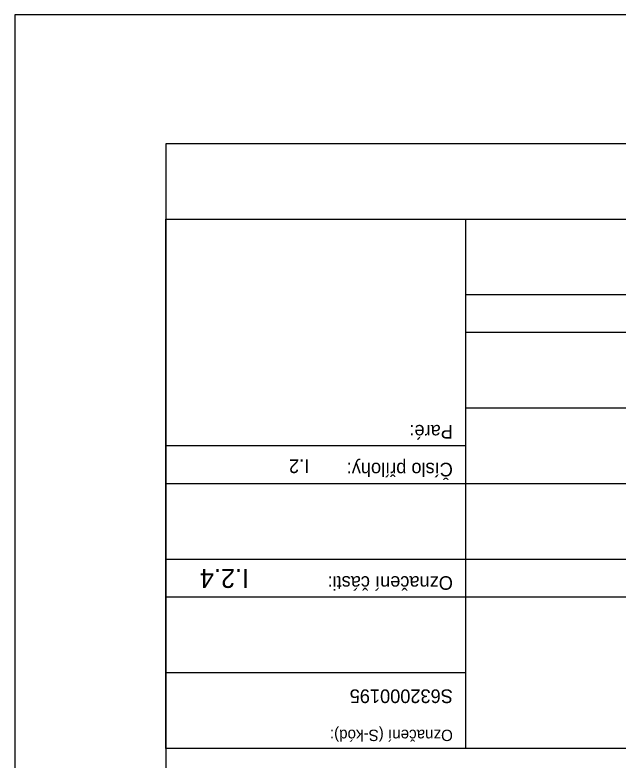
# Model space of a CAD drawing. Extents: x -728452 to -728347, y -1073107 to -1072959.
# Drawn here: x -728452.31 to -728412.4, y -1073008.07 to -1072958.8 of the extents above; entities that cross this region are included whole.
import ezdxf

# ---------------------------------------------------------------- set-up
doc = ezdxf.new("R2010")
doc.units = 0
for name, color, linetype in [('Default', 7, 'Continuous'), ('Dočasný_do_1_roku_PUPFL', 7, 'Continuous'), ('Ořez', 7, 'Continuous')]:
    doc.layers.add(name, color=color, linetype=linetype)

msp = doc.modelspace()

# ---------------------------------------------------------------- linework, layer by layer
at = {"layer": 'Default'}
msp.add_lwpolyline([(-728347.31, -1072958.8), (-728452.31, -1072958.8), (-728452.31, -1073107.3), (-728347.31, -1073107.3)], close=True, dxfattribs=at)
at = {"layer": 'Dočasný_do_1_roku_PUPFL'}
for p, q in [((-728357.317, -1072977.3), (-728422.492, -1072977.3)), ((-728357.317, -1072979.8), (-728422.492, -1072979.8)), ((-728357.317, -1072984.8), (-728422.492, -1072984.8)), ((-728422.492, -1072987.3), (-728442.317, -1072987.3)), ((-728422.492, -1072989.8), (-728442.317, -1072989.8)), ((-728357.317, -1072989.8), (-728422.492, -1072989.8)), ((-728422.492, -1072994.8), (-728442.317, -1072994.8)), ((-728357.317, -1072994.8), (-728422.492, -1072994.8)), ((-728422.492, -1072997.3), (-728442.317, -1072997.3)), ((-728357.317, -1072997.3), (-728422.492, -1072997.3)), ((-728422.492, -1073002.3), (-728442.317, -1073002.3))]:
    msp.add_line(p, q, dxfattribs=at)
for points in [[(-728442.317, -1072972.3), (-728422.492, -1072972.3), (-728422.492, -1073007.3), (-728442.317, -1073007.3)], [(-728357.31, -1073007.3), (-728442.31, -1073007.3), (-728442.31, -1072972.3), (-728357.31, -1072972.3)]]:
    msp.add_lwpolyline(points, close=True, dxfattribs=at)
at = {"layer": 'Ořez'}
msp.add_lwpolyline([(-728357.31, -1073097.3), (-728442.31, -1073097.3), (-728442.31, -1072967.3), (-728357.31, -1072967.3)], close=True, dxfattribs=at)

# ---------------------------------------------------------------- texts
at = {"layer": 'Dočasný_do_1_roku_PUPFL'}
for s, height, p in [('Paré:', 0.9, (-728423.329, -1072985.912)), ('I.2', 0.9, (-728432.833, -1072988.193)), ('Číslo přílohy:', 0.9, (-728423.329, -1072988.412)), ('I.2.4 ', 1.25, (-728436.815, -1072995.437)), ('Označení části:', 0.9, (-728423.329, -1072995.912)), ('S632000195', 0.9, (-728423.329, -1073003.4)), ('Označení (S-kód):', 0.75, (-728423.329, -1073006.062))]:
    msp.add_text(s, height=height, rotation=180, dxfattribs=at).set_placement(p)

doc.saveas('drawing.dxf')
